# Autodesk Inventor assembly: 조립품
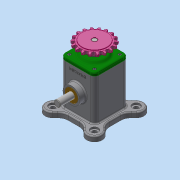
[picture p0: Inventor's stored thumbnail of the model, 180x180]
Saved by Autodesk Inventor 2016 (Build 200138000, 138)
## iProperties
Created: 2019-11
Part Number: 조립품
Material: 일반
Document SubType Name: Assembly
Designer: user
Author: user
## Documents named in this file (11)
- C:\Users\user\Desktop\491109V1007\조립품.iam
- C:\Users\user\Desktop\491109V1007\베어링 6203.ipt
- C:\Users\user\Desktop\491109V1007\본체.ipt
- C:\Users\user\Desktop\491109V1007\볼트 M4.ipt
- C:\Users\user\Desktop\491109V1007\부시.ipt
- C:\Users\user\Desktop\491109V1007\스프로킷.ipt
- C:\Users\user\Desktop\491109V1007\슬라이더.ipt
- C:\Users\user\Desktop\491109V1007\오일 실.ipt
- C:\Users\user\Desktop\491109V1007\커버.ipt
- C:\Users\user\Desktop\491109V1007\키 4 x 4 x 14.ipt
- C:\Users\user\Desktop\491109V1007\편심축.ipt
